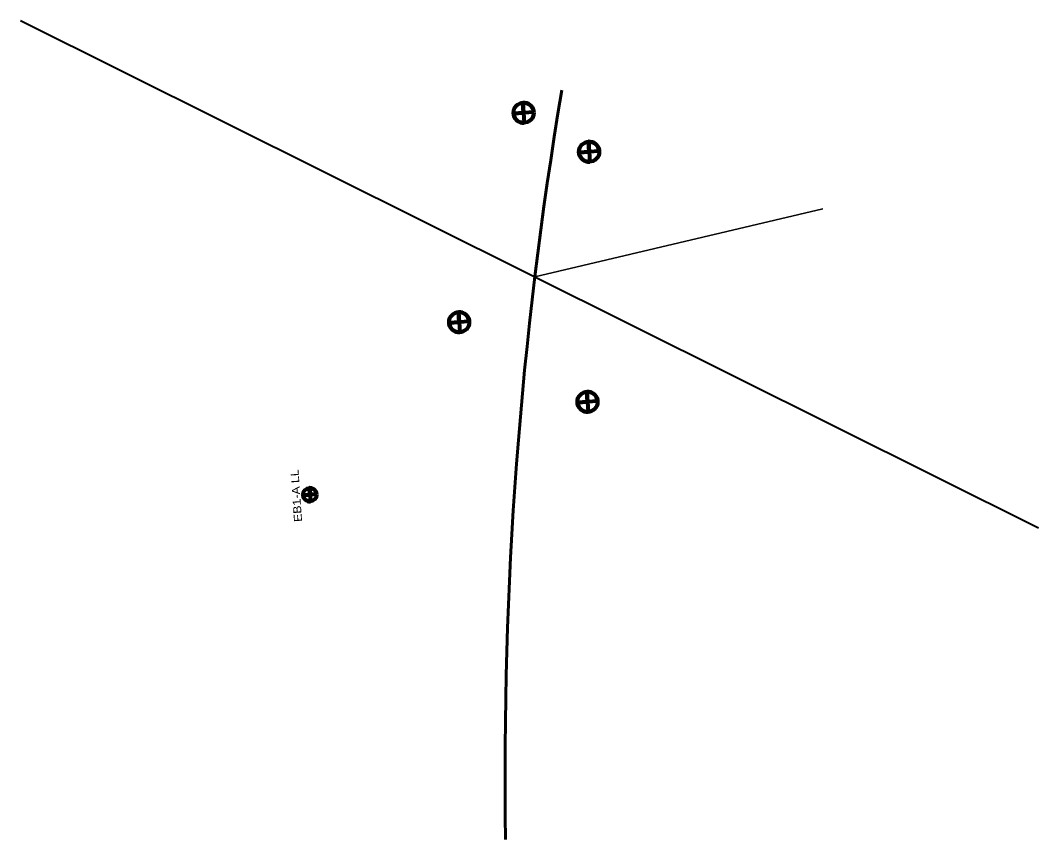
# Model space of a CAD drawing. Extents: x 2399800 to 2400616, y 567351 to 568869.
# Drawn here: x 2399851 to 2400567, y 567351 to 567927 of the extents above; entities that cross this region are included whole.
import ezdxf
from ezdxf.enums import TextEntityAlignment as Align

# ---------------------------------------------------------------- set-up
doc = ezdxf.new("R2010")
doc.units = 0
doc.header["$LTSCALE"] = 2.4
for name, color, linetype, lineweight in [('1', 7, 'Continuous', 40), ('27', 7, 'Continuous', 80), ('4', 7, 'Continuous', 35), ('62', 7, 'Continuous', 60)]:
    doc.layers.add(name, color=color, linetype=linetype, lineweight=lineweight)

msp = doc.modelspace()

# ---------------------------------------------------------------- linework, layer by layer
at = {"layer": '1'}
msp.add_line((2399850.855, 567927.011), (2400566.756, 567569.959), dxfattribs=at)
at = {"layer": '27'}
for p, q in [((2400204.177, 567869.106), (2400205.17, 567854.912)), ((2400197.571, 567861.593), (2400197.576, 567861.514)), ((2400211.771, 567862.505), (2400197.576, 567861.514)), ((2400250.221, 567841.682), (2400251.213, 567827.488)), ((2400243.615, 567834.17), (2400243.62, 567834.09)), ((2400257.814, 567835.081), (2400243.62, 567834.09)), ((2400158.88, 567721.745), (2400159.873, 567707.551)), ((2400152.274, 567714.232), (2400152.279, 567714.153)), ((2400166.474, 567715.144), (2400152.279, 567714.153)), ((2400249.116, 567665.741), (2400250.109, 567651.547)), ((2400242.51, 567658.229), (2400242.515, 567658.149)), ((2400256.709, 567659.14), (2400242.515, 567658.149)), ((2400054.06, 567598.045), (2400054.722, 567588.582)), ((2400049.656, 567593.037), (2400049.66, 567592.984)), ((2400059.123, 567593.644), (2400049.66, 567592.984))]:
    msp.add_line(p, q, dxfattribs=at)
for points in [[(2400211.771, 567862.505), (2400204.673, 567862.01), (2400204.177, 567869.106), (2400204.098, 567869.101)], [(2400197.576, 567861.514), (2400204.673, 567862.01), (2400205.17, 567854.912)], [(2400257.814, 567835.081), (2400250.717, 567834.586), (2400250.221, 567841.682), (2400250.142, 567841.677)], [(2400243.62, 567834.09), (2400250.717, 567834.586), (2400251.213, 567827.488)], [(2400166.474, 567715.144), (2400159.377, 567714.649), (2400158.88, 567721.745), (2400158.802, 567721.739)], [(2400152.279, 567714.153), (2400159.377, 567714.649), (2400159.873, 567707.551)], [(2400256.709, 567659.14), (2400249.612, 567658.645), (2400249.116, 567665.741), (2400249.037, 567665.736)], [(2400242.515, 567658.149), (2400249.612, 567658.645), (2400250.109, 567651.547)], [(2400059.123, 567593.644), (2400054.391, 567593.314), (2400054.06, 567598.045), (2400054.007, 567598.041)], [(2400049.66, 567592.984), (2400054.391, 567593.314), (2400054.722, 567588.582)]]:
    msp.add_lwpolyline(points, dxfattribs=at)
for centre, radius in [((2400204.673, 567862.01), 7.114), ((2400250.717, 567834.586), 7.114), ((2400159.376, 567714.648), 7.114), ((2400249.612, 567658.645), 7.114), ((2400054.391, 567593.314), 4.743)]:
    msp.add_circle(centre, radius, dxfattribs=at)
for centre, radius, start, end in [((2400204.673, 567862.01), 7.114, 4, 94.64426), ((2400204.673, 567862.01), 7.114, 183.35573, 274), ((2400250.717, 567834.586), 7.114, 4, 94.64426), ((2400250.717, 567834.586), 7.114, 183.35573, 274), ((2400159.376, 567714.648), 7.114, 4, 94.64426), ((2400159.376, 567714.648), 7.114, 183.35573, 274), ((2400249.612, 567658.645), 7.114, 4, 94.64426), ((2400249.612, 567658.645), 7.114, 183.35573, 274), ((2400054.391, 567593.314), 4.743, 4, 94.64426), ((2400054.391, 567593.314), 4.743, 183.35573, 274)]:
    msp.add_arc(centre, radius, start, end, dxfattribs=at)
at = {"layer": '4'}
msp.add_line((2400212.566, 567746.61), (2400415.038, 567794.425), dxfattribs=at)
at = {"layer": '62'}
msp.add_arc((2403091.606, 567398.578), 2900, 170.48821, 180.94658, dxfattribs=at)

# ---------------------------------------------------------------- texts
at = {"layer": '27', "width": 1.15}
msp.add_text('EB1-A LL', height=5.625, rotation=94, dxfattribs=at).set_placement((2400047.638, 567592.83), align=Align.CENTER)

doc.saveas('drawing.dxf')
